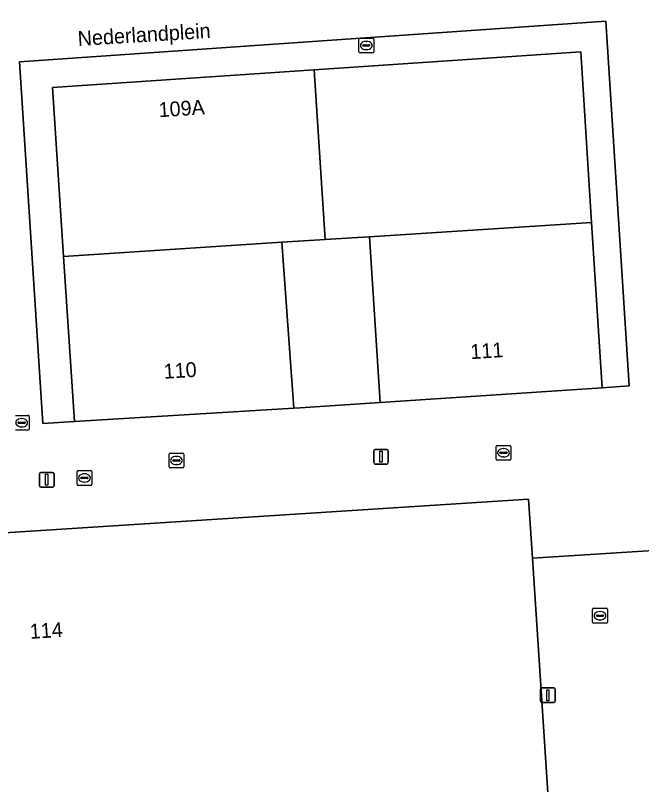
# Model space of a CAD drawing. Extents: x 159680 to 160786, y 387323 to 388340.
# Drawn here: x 160270.6 to 160312.9, y 387740.3 to 387792.3 of the extents above; entities that cross this region are included whole.
import ezdxf

# ---------------------------------------------------------------- set-up
doc = ezdxf.new("R2010")
doc.units = 0
for name, color, linetype in [('IMGEO_Brandkraan', 7, 'Continuous'), ('IMGEO_Kolk', 7, 'Continuous'), ('IMGEO_Lichtmast', 7, 'Continuous'), ('IMGEO_Openbare_ruimte_label', 7, 'Continuous'), ('IMGEO_Pand', 7, 'Continuous'), ('IMGEO_Pand_nummerreeks', 7, 'Continuous'), ('IMGEO_Rioolput', 7, 'Continuous'), ('IMGEO_Voetpad_open', 7, 'Continuous')]:
    doc.layers.add(name, color=color, linetype=linetype)

msp = doc.modelspace()

# ---------------------------------------------------------------- linework, layer by layer
at = {"layer": 'IMGEO_Brandkraan'}
for p, q in [((160293.815, 387789.873), (160293.815, 387790.725)), ((160293.89, 387790.799), (160294.742, 387790.799)), ((160294.816, 387790.725), (160294.816, 387789.873)), ((160294.074, 387790.293), (160294.074, 387790.305)), ((160294.512, 387790.256), (160294.114, 387790.256)), ((160294.117, 387790.342), (160294.515, 387790.342)), ((160294.303, 387790.579), (160294.328, 387790.579)), ((160294.558, 387790.305), (160294.558, 387790.293)), ((160294.742, 387789.799), (160293.89, 387789.799)), ((160294.326, 387790.019), (160294.301, 387790.019))]:
    msp.add_line(p, q, dxfattribs=at)
for points in [[(160293.815, 387789.873), (160293.815, 387790.725)], [(160293.89, 387790.799), (160294.742, 387790.799)], [(160294.816, 387790.725), (160294.816, 387789.873)], [(160294.742, 387789.799), (160293.89, 387789.799)]]:
    msp.add_lwpolyline(points, dxfattribs=at)
for centre, radius, start, end in [((160293.892, 387790.723), 0.0765, 91.552, 178.448), ((160293.892, 387790.723), 0.0765, 91.552, 178.448), ((160294.74, 387790.723), 0.0765, 1.552, 88.448), ((160294.74, 387790.723), 0.0765, 1.552, 88.448), ((160294.114, 387790.302), 0.0403, 85.8775, 175.7526), ((160294.111, 387790.292), 0.0366, 178.938, 274.7102), ((160294.515, 387790.299), 0.043, 264.8664, 352.4533), ((160294.519, 387790.304), 0.0386, 1.7309, 96.639), ((160293.892, 387789.875), 0.0765, 181.552, 268.448), ((160293.892, 387789.875), 0.0765, 181.552, 268.448), ((160294.74, 387789.875), 0.0765, 271.552, 358.448), ((160294.74, 387789.875), 0.0765, 271.552, 358.448)]:
    msp.add_arc(centre, radius, start, end, dxfattribs=at)
for centre, major_axis, ratio, start_param, end_param in [((160294.302, 387790.299), (-0.387, 0.002), 0.722429, 4.712389, 7.853982), ((160294.327, 387790.299), (-0.39, 0.002), 0.717154, 1.570796, 4.712389)]:
    msp.add_ellipse(centre, major_axis=major_axis, ratio=ratio, start_param=start_param, end_param=end_param, dxfattribs=at)
at = {"layer": 'IMGEO_Kolk'}
for p, q in [((160280.978, 387761.826), (160280.978, 387762.678)), ((160281.053, 387762.752), (160281.905, 387762.752)), ((160281.979, 387762.678), (160281.979, 387761.826)), ((160281.237, 387762.246), (160281.237, 387762.258)), ((160281.675, 387762.209), (160281.277, 387762.209)), ((160281.28, 387762.295), (160281.678, 387762.295)), ((160281.466, 387762.532), (160281.491, 387762.532)), ((160281.721, 387762.258), (160281.721, 387762.246)), ((160281.905, 387761.752), (160281.053, 387761.752)), ((160281.489, 387761.972), (160281.464, 387761.972)), ((160309.692, 387752.262), (160310.544, 387752.262)), ((160309.617, 387751.336), (160309.617, 387752.188)), ((160309.876, 387751.756), (160309.876, 387751.768)), ((160310.314, 387751.719), (160309.916, 387751.719)), ((160309.919, 387751.805), (160310.317, 387751.805)), ((160310.105, 387752.042), (160310.13, 387752.042)), ((160310.36, 387751.768), (160310.36, 387751.756)), ((160310.618, 387752.188), (160310.618, 387751.336)), ((160310.544, 387751.262), (160309.692, 387751.262)), ((160310.128, 387751.482), (160310.103, 387751.482))]:
    msp.add_line(p, q, dxfattribs=at)
for points in [[(160280.978, 387761.826), (160280.978, 387762.678)], [(160281.053, 387762.752), (160281.905, 387762.752)], [(160281.979, 387762.678), (160281.979, 387761.826)], [(160281.905, 387761.752), (160281.053, 387761.752)], [(160309.692, 387752.262), (160310.544, 387752.262)], [(160309.617, 387751.336), (160309.617, 387752.188)], [(160310.618, 387752.188), (160310.618, 387751.336)], [(160310.544, 387751.262), (160309.692, 387751.262)]]:
    msp.add_lwpolyline(points, dxfattribs=at)
for centre, radius, start, end in [((160281.055, 387762.676), 0.0765, 91.552, 178.448), ((160281.055, 387762.676), 0.0765, 91.552, 178.448), ((160281.903, 387762.676), 0.0765, 1.552, 88.448), ((160281.903, 387762.676), 0.0765, 1.552, 88.448), ((160281.277, 387762.255), 0.0403, 85.8775, 175.7526), ((160281.274, 387762.245), 0.0366, 178.938, 274.7102), ((160281.678, 387762.252), 0.043, 264.8664, 352.4533), ((160281.682, 387762.257), 0.0386, 1.7309, 96.639), ((160281.055, 387761.828), 0.0765, 181.552, 268.448), ((160281.055, 387761.828), 0.0765, 181.552, 268.448), ((160281.903, 387761.828), 0.0765, 271.552, 358.448), ((160281.903, 387761.828), 0.0765, 271.552, 358.448), ((160309.694, 387752.186), 0.0765, 91.552, 178.448), ((160309.694, 387752.186), 0.0765, 91.552, 178.448), ((160310.542, 387752.186), 0.0765, 1.552, 88.448), ((160310.542, 387752.186), 0.0765, 1.552, 88.448), ((160309.916, 387751.765), 0.0403, 85.8775, 175.7526), ((160309.913, 387751.755), 0.0366, 178.938, 274.7102), ((160310.317, 387751.762), 0.043, 264.8664, 352.4533), ((160310.321, 387751.767), 0.0386, 1.7309, 96.639), ((160309.694, 387751.338), 0.0765, 181.552, 268.448), ((160309.694, 387751.338), 0.0765, 181.552, 268.448), ((160310.542, 387751.338), 0.0765, 271.552, 358.448), ((160310.542, 387751.338), 0.0765, 271.552, 358.448)]:
    msp.add_arc(centre, radius, start, end, dxfattribs=at)
for centre, major_axis, ratio, start_param, end_param in [((160281.465, 387762.252), (-0.387, 0.002), 0.722429, 4.712389, 7.853982), ((160281.49, 387762.252), (-0.39, 0.002), 0.717154, 1.570796, 4.712389), ((160310.104, 387751.762), (-0.387, 0.002), 0.722429, 4.712389, 7.853982), ((160310.129, 387751.762), (-0.39, 0.002), 0.717154, 1.570796, 4.712389)]:
    msp.add_ellipse(centre, major_axis=major_axis, ratio=ratio, start_param=start_param, end_param=end_param, dxfattribs=at)
at = {"layer": 'IMGEO_Lichtmast'}
for p, q in [((160294.815, 387762.105), (160294.815, 387762.905)), ((160294.815, 387762.905), (160294.815, 387762.105)), ((160294.915, 387763.005), (160295.705, 387763.005)), ((160295.705, 387763.005), (160294.915, 387763.005)), ((160295.805, 387762.905), (160295.805, 387762.105)), ((160295.805, 387762.105), (160295.805, 387762.905)), ((160295.705, 387762.005), (160294.915, 387762.005)), ((160294.915, 387762.005), (160295.705, 387762.005)), ((160272.215, 387760.55), (160272.215, 387761.35)), ((160272.215, 387761.35), (160272.215, 387760.55)), ((160272.315, 387761.45), (160273.105, 387761.45)), ((160273.105, 387761.45), (160272.315, 387761.45)), ((160273.205, 387761.35), (160273.205, 387760.55)), ((160273.205, 387760.55), (160273.205, 387761.35)), ((160273.105, 387760.45), (160272.315, 387760.45)), ((160272.315, 387760.45), (160273.105, 387760.45)), ((160306.095, 387745.988), (160306.095, 387746.788)), ((160306.095, 387746.788), (160306.095, 387745.988)), ((160306.195, 387746.888), (160306.985, 387746.888)), ((160306.985, 387746.888), (160306.195, 387746.888)), ((160307.085, 387746.788), (160307.085, 387745.988)), ((160307.085, 387745.988), (160307.085, 387746.788)), ((160306.985, 387745.888), (160306.195, 387745.888)), ((160306.195, 387745.888), (160306.985, 387745.888))]:
    msp.add_line(p, q, dxfattribs=at)
for points in [[(160295.235, 387762.88), (160295.385, 387762.88), (160295.385, 387762.13), (160295.235, 387762.13), (160295.235, 387762.88)], [(160272.635, 387761.325), (160272.785, 387761.325), (160272.785, 387760.575), (160272.635, 387760.575), (160272.635, 387761.325)], [(160306.515, 387746.763), (160306.665, 387746.763), (160306.665, 387746.013), (160306.515, 387746.013), (160306.515, 387746.763)]]:
    msp.add_lwpolyline(points, dxfattribs=at)
for centre, start, end in [((160294.915, 387762.905), 90, 180), ((160294.915, 387762.905), 90, 180), ((160295.705, 387762.905), 0, 90), ((160295.705, 387762.905), 360, 90), ((160294.915, 387762.105), 180, 270), ((160294.915, 387762.105), 180, 270), ((160295.705, 387762.105), 270, 0), ((160295.705, 387762.105), 270, 0), ((160272.315, 387761.35), 90, 180), ((160272.315, 387761.35), 90, 180), ((160273.105, 387761.35), 0, 90), ((160273.105, 387761.35), 360, 90), ((160272.315, 387760.55), 180, 270), ((160272.315, 387760.55), 180, 270), ((160273.105, 387760.55), 270, 0), ((160273.105, 387760.55), 270, 0), ((160306.195, 387746.788), 90, 180), ((160306.195, 387746.788), 90, 180), ((160306.985, 387746.788), 0, 90), ((160306.985, 387746.788), 360, 90), ((160306.195, 387745.988), 180, 270), ((160306.195, 387745.988), 180, 270), ((160306.985, 387745.988), 270, 0), ((160306.985, 387745.988), 270, 0)]:
    msp.add_arc(centre, 0.1, start, end, dxfattribs=at)
at = {"layer": 'IMGEO_Pand'}
for points in [[(160308.82, 387789.881), (160290.797, 387788.659), (160291.541, 387777.185), (160293.729, 387777.326), (160294.536, 387777.378), (160309.551, 387778.345)], [(160290.797, 387788.659), (160273.096, 387787.458), (160273.844, 387776.045), (160288.604, 387776.996), (160291.541, 387777.185)], [(160294.536, 387777.378), (160295.246, 387766.171), (160310.259, 387767.165), (160309.551, 387778.345)], [(160294.536, 387777.378), (160293.729, 387777.326), (160291.541, 387777.185), (160288.604, 387776.996), (160289.405, 387765.786), (160289.84, 387765.813), (160295.246, 387766.171)], [(160288.604, 387776.996), (160273.844, 387776.045), (160274.577, 387764.876), (160289.405, 387765.786)]]:
    msp.add_lwpolyline(points, close=True, dxfattribs=at)
msp.add_lwpolyline([(160253.589, 387733.768), (160276.691, 387735.258), (160280.662, 387735.514), (160306.345, 387737.171), (160306.755, 387737.197), (160306.743, 387737.371), (160305.552, 387755.65), (160305.293, 387759.637), (160267.045, 387757.179), (160248.612, 387755.995), (160248.646, 387755.434)], dxfattribs=at)
at = {"layer": 'IMGEO_Rioolput'}
for p, q in [((160270.59, 387765.303), (160271.442, 387765.303)), ((160271.516, 387765.229), (160271.516, 387764.377)), ((160270.774, 387764.797), (160270.774, 387764.809)), ((160271.212, 387764.76), (160270.814, 387764.76)), ((160270.817, 387764.846), (160271.215, 387764.846)), ((160271.003, 387765.083), (160271.028, 387765.083)), ((160271.258, 387764.809), (160271.258, 387764.797)), ((160271.442, 387764.303), (160270.59, 387764.303)), ((160271.026, 387764.523), (160271.001, 387764.523)), ((160303.094, 387762.349), (160303.094, 387763.201)), ((160303.169, 387763.275), (160304.021, 387763.275)), ((160304.095, 387763.201), (160304.095, 387762.349)), ((160303.353, 387762.769), (160303.353, 387762.781)), ((160303.791, 387762.732), (160303.393, 387762.732)), ((160303.396, 387762.818), (160303.794, 387762.818)), ((160303.582, 387763.055), (160303.607, 387763.055)), ((160303.837, 387762.781), (160303.837, 387762.769)), ((160304.021, 387762.275), (160303.169, 387762.275)), ((160303.605, 387762.495), (160303.58, 387762.495)), ((160274.757, 387760.645), (160274.757, 387761.497)), ((160274.832, 387761.571), (160275.684, 387761.571)), ((160275.016, 387761.065), (160275.016, 387761.077)), ((160275.059, 387761.114), (160275.457, 387761.114)), ((160275.245, 387761.351), (160275.27, 387761.351)), ((160275.5, 387761.077), (160275.5, 387761.065)), ((160275.758, 387761.497), (160275.758, 387760.645)), ((160275.684, 387760.571), (160274.832, 387760.571)), ((160275.454, 387761.028), (160275.056, 387761.028)), ((160275.268, 387760.791), (160275.243, 387760.791))]:
    msp.add_line(p, q, dxfattribs=at)
for points in [[(160270.59, 387765.303), (160271.442, 387765.303)], [(160271.516, 387765.229), (160271.516, 387764.377)], [(160271.442, 387764.303), (160270.59, 387764.303)], [(160303.094, 387762.349), (160303.094, 387763.201)], [(160303.169, 387763.275), (160304.021, 387763.275)], [(160304.095, 387763.201), (160304.095, 387762.349)], [(160304.021, 387762.275), (160303.169, 387762.275)], [(160274.757, 387760.645), (160274.757, 387761.497)], [(160274.832, 387761.571), (160275.684, 387761.571)], [(160275.758, 387761.497), (160275.758, 387760.645)], [(160275.684, 387760.571), (160274.832, 387760.571)]]:
    msp.add_lwpolyline(points, dxfattribs=at)
for centre, radius, start, end in [((160271.44, 387765.227), 0.0765, 1.552, 88.448), ((160271.44, 387765.227), 0.0765, 1.552, 88.448), ((160270.814, 387764.806), 0.0403, 85.8775, 175.7526), ((160270.811, 387764.796), 0.0366, 178.938, 274.7102), ((160271.215, 387764.803), 0.043, 264.8664, 352.4533), ((160271.219, 387764.808), 0.0386, 1.7309, 96.639), ((160271.44, 387764.379), 0.0765, 271.552, 358.448), ((160271.44, 387764.379), 0.0765, 271.552, 358.448), ((160303.171, 387763.199), 0.0765, 91.552, 178.448), ((160303.171, 387763.199), 0.0765, 91.552, 178.448), ((160304.019, 387763.199), 0.0765, 1.552, 88.448), ((160304.019, 387763.199), 0.0765, 1.552, 88.448), ((160303.393, 387762.778), 0.0403, 85.8775, 175.7526), ((160303.39, 387762.768), 0.0366, 178.938, 274.7102), ((160303.794, 387762.775), 0.043, 264.8664, 352.4533), ((160303.798, 387762.78), 0.0386, 1.7309, 96.639), ((160303.171, 387762.351), 0.0765, 181.552, 268.448), ((160303.171, 387762.351), 0.0765, 181.552, 268.448), ((160304.019, 387762.351), 0.0765, 271.552, 358.448), ((160304.019, 387762.351), 0.0765, 271.552, 358.448), ((160274.834, 387761.495), 0.0765, 91.552, 178.448), ((160274.834, 387761.495), 0.0765, 91.552, 178.448), ((160275.056, 387761.074), 0.0403, 85.8775, 175.7526), ((160275.461, 387761.076), 0.0386, 1.7309, 96.639), ((160275.682, 387761.495), 0.0765, 1.552, 88.448), ((160275.682, 387761.495), 0.0765, 1.552, 88.448), ((160274.834, 387760.647), 0.0765, 181.552, 268.448), ((160274.834, 387760.647), 0.0765, 181.552, 268.448), ((160275.053, 387761.064), 0.0366, 178.938, 274.7102), ((160275.457, 387761.071), 0.043, 264.8664, 352.4533), ((160275.682, 387760.647), 0.0765, 271.552, 358.448), ((160275.682, 387760.647), 0.0765, 271.552, 358.448)]:
    msp.add_arc(centre, radius, start, end, dxfattribs=at)
for centre, major_axis, ratio, start_param, end_param in [((160271.002, 387764.803), (-0.387, 0.002), 0.722429, 4.712389, 7.853982), ((160271.027, 387764.803), (-0.39, 0.002), 0.717154, 1.570796, 4.712389), ((160303.581, 387762.775), (-0.387, 0.002), 0.722429, 4.712389, 7.853982), ((160303.606, 387762.775), (-0.39, 0.002), 0.717154, 1.570796, 4.712389), ((160275.244, 387761.071), (-0.387, 0.002), 0.722429, 4.712389, 7.853982), ((160275.269, 387761.071), (-0.39, 0.002), 0.717154, 1.570796, 4.712389)]:
    msp.add_ellipse(centre, major_axis=major_axis, ratio=ratio, start_param=start_param, end_param=end_param, dxfattribs=at)
at = {"layer": 'IMGEO_Voetpad_open'}
for points in [[(160267.045, 387757.179), (160305.293, 387759.637), (160305.552, 387755.65), (160314.074, 387756.196), (160314.413, 387750.902), (160314.471, 387750), (160314.558, 387748.644), (160316.917, 387748.799), (160321.422, 387749.095), (160321.394, 387749.39), (160322.546, 387749.466), (160322.428, 387751.404), (160322.036, 387757.833), (160322.017, 387758.116), (160319.097, 387801.761)], [(160322.891, 387743.823), (160321.76, 387743.808), (160321.744, 387744.061), (160317.251, 387743.782), (160316.917, 387748.799), (160314.558, 387748.644), (160314.471, 387750), (160314.413, 387750.902), (160314.074, 387756.196), (160305.552, 387755.65), (160306.743, 387737.371)]]:
    msp.add_lwpolyline(points, dxfattribs=at)
for points in [[(160309.551, 387778.345), (160310.259, 387767.165), (160312.09, 387767.288), (160310.506, 387791.95), (160270.87, 387789.192), (160272.44, 387764.745), (160274.577, 387764.876), (160273.844, 387776.045), (160273.096, 387787.458), (160290.797, 387788.659), (160308.82, 387789.881)], [(160274.577, 387764.876), (160272.44, 387764.745), (160270.87, 387789.192), (160310.506, 387791.95), (160312.09, 387767.288), (160310.259, 387767.165), (160295.246, 387766.171), (160289.84, 387765.813), (160289.405, 387765.786)]]:
    msp.add_lwpolyline(points, close=True, dxfattribs=at)

# ---------------------------------------------------------------- texts
at = {"layer": 'IMGEO_Openbare_ruimte_label'}
msp.add_text('Nederlandplein', height=1, rotation=3.4977, dxfattribs=at).set_placement((160274.833, 387790.263))
at = {"layer": 'IMGEO_Pand_nummerreeks'}
for s, rotation, p in [('109A', 3.6841, (160280.304, 387785.447)), ('111', 3.8275, (160301.381, 387769.097)), ('110', 3.5119, (160280.645, 387767.774)), ('114', 3.6522, (160271.587, 387750.193))]:
    msp.add_text(s, height=1, rotation=rotation, dxfattribs=at).set_placement(p)

doc.saveas('drawing.dxf')
